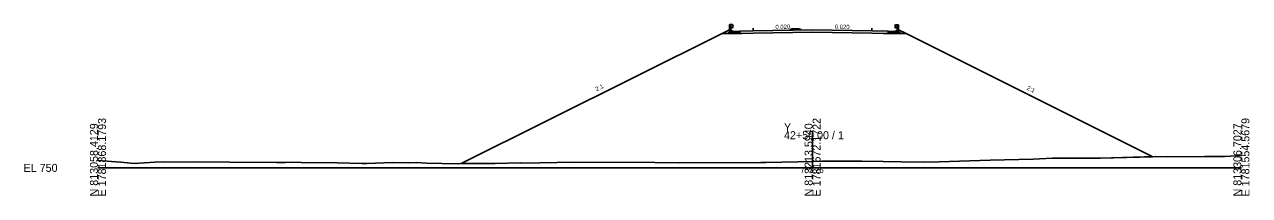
# Model space of a CAD drawing. Extents: x -12583 to 5303, y -44 to 25667.
# Drawn here: x 2874.3 to 3302.8, y 2990.3 to 3050.2 of the extents above; entities that cross this region are included whole.
import ezdxf

# ---------------------------------------------------------------- set-up
doc = ezdxf.new("R2010")
doc.units = 0
for name, color, linetype in [('Exist Cross Section Cell', 7, 'Continuous'), ('Exist XS Center Line Elevation Label', 7, 'Continuous'), ('Exist XS Ground Line', 7, 'Continuous'), ('Prop Conc 5in Monolithic Surface Mount Island', 7, 'Continuous'), ('Prop XS Dump Level', 7, 'Continuous'), ('Prop XS Earthwork Shape', 7, 'Continuous'), ('Prop XS EOT Tick Mark', 7, 'Continuous'), ('Prop XS Finish Grade', 7, 'Continuous'), ('Prop XS Finish Grade CurbGutter', 7, 'Continuous'), ('Prop XS Finish Grade Earthwork', 7, 'Continuous'), ('Prop XS Finish Grade Paved Shoulder', 7, 'Continuous'), ('Prop XS Finish Grade Pavement', 7, 'Continuous'), ('Prop XS Guardrail', 7, 'Continuous'), ('Prop XS Pvmt Edge Slope', 7, 'Continuous'), ('Prop XS SE Text', 7, 'Continuous'), ('Prop XS Side Slope Text', 7, 'Continuous'), ('Prop XS Subgrade CurbGutter', 7, 'Continuous'), ('Prop XS Subgrade Earthwork', 7, 'Continuous')]:
    doc.layers.add(name, color=color, linetype=linetype)

msp = doc.modelspace()

# ---------------------------------------------------------------- linework, layer by layer
at = {"layer": 'Exist Cross Section Cell'}
for p, q in [((3150, 3000), (3150, 3012.85)), ((2900, 3000), (3150, 3000)), ((3150, 3000), (3300, 3000))]:
    msp.add_line(p, q, dxfattribs=at)
at = {"layer": 'Exist XS Ground Line'}
for p, q in [((3294.2, 3004), (3300, 3004.28)), ((2900, 3002.64), (2907.99, 3001.98)), ((2907.99, 3001.98), (2912.67, 3001.49)), ((2912.67, 3001.49), (2919.88, 3001.96)), ((2919.88, 3001.96), (2923.39, 3002.14)), ((2923.39, 3002.14), (2932.14, 3002.04)), ((2932.14, 3002.04), (2934.84, 3002.06)), ((2934.84, 3002.06), (2946.08, 3002)), ((2946.08, 3002), (2962.58, 3001.93)), ((2962.58, 3001.93), (2965.66, 3001.88)), ((2965.66, 3001.88), (2967.65, 3001.95)), ((2967.65, 3001.95), (2971.09, 3001.87)), ((2971.09, 3001.87), (2983.73, 3001.78)), ((2983.73, 3001.78), (2992.42, 3001.51)), ((2992.42, 3001.51), (2993.18, 3001.5)), ((2993.18, 3001.5), (2994.07, 3001.49)), ((2994.07, 3001.49), (3003.1, 3001.84)), ((3003.1, 3001.84), (3008.81, 3001.75)), ((3008.81, 3001.75), (3011.36, 3001.83)), ((3011.36, 3001.83), (3014.98, 3001.68)), ((3014.98, 3001.68), (3025.79, 3001.47)), ((3025.79, 3001.47), (3038.97, 3001.58)), ((3038.97, 3001.58), (3047.75, 3001.78)), ((3047.75, 3001.78), (3048.64, 3001.61)), ((3048.64, 3001.61), (3066.53, 3002.05)), ((3066.53, 3002.05), (3094.86, 3001.86)), ((3094.86, 3001.86), (3103.38, 3001.81)), ((3103.38, 3001.81), (3131.91, 3001.9)), ((3131.91, 3001.9), (3132.7, 3001.9)), ((3132.7, 3001.9), (3133.6, 3001.91)), ((3133.6, 3001.91), (3144.89, 3002.16)), ((3144.89, 3002.16), (3150, 3002.25)), ((3150, 3002.25), (3153.26, 3002.3)), ((3153.26, 3002.3), (3159.58, 3002.33)), ((3159.58, 3002.33), (3167.17, 3002.31)), ((3167.17, 3002.31), (3174.64, 3002.27)), ((3174.64, 3002.27), (3181.1, 3002.16)), ((3181.1, 3002.16), (3188.89, 3001.97)), ((3188.89, 3001.97), (3194.3, 3002.12)), ((3194.3, 3002.12), (3212.11, 3002.67)), ((3212.11, 3002.67), (3227.2, 3003.1)), ((3227.2, 3003.1), (3233.88, 3003.43)), ((3233.88, 3003.43), (3246.46, 3003.35)), ((3246.46, 3003.35), (3250.71, 3003.43)), ((3250.71, 3003.43), (3269.82, 3003.93)), ((3269.82, 3003.93), (3274.03, 3003.9)), ((3274.03, 3003.9), (3287.22, 3003.93)), ((3287.22, 3003.93), (3292.32, 3003.94)), ((3292.32, 3003.94), (3294.2, 3004))]:
    msp.add_line(p, q, dxfattribs=at)
at = {"layer": 'Prop Conc 5in Monolithic Surface Mount Island'}
for p, q in [((3142, 3048.39), (3142.74, 3048.66)), ((3142, 3048.22), (3142, 3048.39)), ((3142.74, 3048.66), (3143.99, 3048.71)), ((3145.24, 3048.71), (3143.99, 3048.71)), ((3146, 3048.47), (3145.24, 3048.71)), ((3146, 3048.3), (3146, 3048.47))]:
    msp.add_line(p, q, dxfattribs=at)
at = {"layer": 'Prop XS Dump Level'}
for p, q in [((3129.25, 3047.97), (3150, 3048.38)), ((3150, 3048.38), (3170.75, 3047.97))]:
    msp.add_line(p, q, dxfattribs=at)
at = {"layer": 'Prop XS Earthwork Shape'}
msp.add_lwpolyline([(3174.64, 3002.27), (3181.1, 3002.16), (3188.89, 3001.97), (3194.3, 3002.12), (3212.11, 3002.67), (3227.2, 3003.1), (3233.88, 3003.43), (3246.46, 3003.35), (3250.71, 3003.43), (3268.99, 3003.91), (3182.68, 3047.06), (3180.81, 3047.06), (3176.42, 3047.06), (3174.75, 3047.1), (3170.75, 3047.18), (3150, 3047.59), (3129.25, 3047.18), (3125.25, 3047.1), (3124.58, 3047.08), (3120.18, 3047.08), (3118.31, 3047.08), (3027.11, 3001.48), (3038.97, 3001.58), (3047.75, 3001.78), (3048.64, 3001.61), (3066.53, 3002.05), (3094.86, 3001.86), (3103.38, 3001.81), (3131.91, 3001.9), (3132.7, 3001.9), (3133.6, 3001.91), (3144.89, 3002.16), (3150, 3002.25), (3153.26, 3002.3), (3159.58, 3002.33), (3167.17, 3002.31)], close=True, dxfattribs=at)
at = {"layer": 'Prop XS EOT Tick Mark'}
for p, q in [((3129.25, 3047.97), (3129.25, 3048.97)), ((3170.75, 3047.97), (3170.75, 3048.97))]:
    msp.add_line(p, q, dxfattribs=at)
at = {"layer": 'Prop XS Finish Grade'}
for p, q in [((3120.97, 3048.41), (3118.31, 3047.08)), ((3121.56, 3048.12), (3120.97, 3048.41)), ((3179.44, 3048.1), (3180.02, 3048.39)), ((3182.68, 3047.06), (3180.02, 3048.39))]:
    msp.add_line(p, q, dxfattribs=at)
at = {"layer": 'Prop XS Finish Grade CurbGutter'}
for p, q in [((3122.25, 3047.78), (3121.56, 3048.12)), ((3124.58, 3047.87), (3122.25, 3047.78)), ((3176.42, 3047.86), (3178.75, 3047.76)), ((3178.75, 3047.76), (3179.44, 3048.1))]:
    msp.add_line(p, q, dxfattribs=at)
at = {"layer": 'Prop XS Finish Grade Earthwork'}
for p, q in [((3118.31, 3047.08), (3027.11, 3001.48)), ((3182.68, 3047.06), (3268.99, 3003.91))]:
    msp.add_line(p, q, dxfattribs=at)
at = {"layer": 'Prop XS Finish Grade Paved Shoulder'}
for p, q in [((3129.25, 3047.97), (3124.58, 3047.87)), ((3170.75, 3047.97), (3176.42, 3047.86))]:
    msp.add_line(p, q, dxfattribs=at)
at = {"layer": 'Prop XS Finish Grade Pavement'}
for p, q in [((3129.25, 3047.97), (3150, 3048.38)), ((3150, 3048.38), (3170.75, 3047.97)), ((3150, 3048.38), (3170.75, 3047.97))]:
    msp.add_line(p, q, dxfattribs=at)
at = {"layer": 'Prop XS Guardrail'}
for p, q in [((3120.93, 3050.18), (3121.43, 3050.18)), ((3120.93, 3047.68), (3120.93, 3050.18)), ((3121.43, 3050.18), (3121.93, 3050.18)), ((3121.43, 3050.18), (3121.43, 3047.68)), ((3121.93, 3049.04), (3121.43, 3049.04)), ((3121.93, 3050.18), (3122.22, 3049.98)), ((3122.22, 3049.86), (3121.93, 3049.66)), ((3121.93, 3049.66), (3121.93, 3049.56)), ((3121.93, 3049.56), (3122.22, 3049.36)), ((3122.22, 3049.24), (3121.93, 3049.04)), ((3122.22, 3049.98), (3122.25, 3049.92)), ((3122.25, 3049.92), (3122.22, 3049.86)), ((3122.22, 3049.36), (3122.25, 3049.3)), ((3122.25, 3049.3), (3122.22, 3049.24)), ((3178.78, 3049.96), (3178.75, 3049.9)), ((3178.75, 3049.9), (3178.78, 3049.84)), ((3178.78, 3049.34), (3178.75, 3049.28)), ((3178.75, 3049.28), (3178.78, 3049.22)), ((3179.07, 3050.16), (3178.78, 3049.96)), ((3178.78, 3049.84), (3179.07, 3049.64)), ((3179.07, 3049.54), (3178.78, 3049.34)), ((3178.78, 3049.22), (3179.07, 3049.02)), ((3179.57, 3050.16), (3179.07, 3050.16)), ((3179.07, 3049.64), (3179.07, 3049.54)), ((3179.07, 3049.02), (3179.57, 3049.02)), ((3180.07, 3050.16), (3179.57, 3050.16)), ((3179.57, 3050.16), (3179.57, 3047.66)), ((3180.07, 3047.66), (3180.07, 3050.16))]:
    msp.add_line(p, q, dxfattribs=at)
at = {"layer": 'Prop XS Pvmt Edge Slope'}
for p, q in [((3120.56, 3047.45), (3120.18, 3047.08)), ((3121.56, 3047.45), (3120.56, 3047.45)), ((3179.44, 3047.44), (3180.44, 3047.44)), ((3180.44, 3047.44), (3180.81, 3047.06))]:
    msp.add_line(p, q, dxfattribs=at)
at = {"layer": 'Prop XS Subgrade CurbGutter'}
for p, q in [((3121.56, 3047.45), (3121.56, 3048.12)), ((3124.58, 3047.45), (3121.56, 3047.45)), ((3124.58, 3047.87), (3124.58, 3047.45)), ((3176.42, 3047.86), (3176.42, 3047.44)), ((3176.42, 3047.44), (3179.44, 3047.44)), ((3179.44, 3047.44), (3179.44, 3048.1))]:
    msp.add_line(p, q, dxfattribs=at)
at = {"layer": 'Prop XS Subgrade Earthwork'}
for p, q in [((3120.18, 3047.08), (3118.31, 3047.08)), ((3124.58, 3047.08), (3120.18, 3047.08)), ((3125.25, 3047.1), (3124.58, 3047.08)), ((3129.25, 3047.18), (3125.25, 3047.1)), ((3150, 3047.59), (3129.25, 3047.18)), ((3170.75, 3047.18), (3150, 3047.59)), ((3170.75, 3047.18), (3174.75, 3047.1)), ((3174.75, 3047.1), (3176.42, 3047.06)), ((3176.42, 3047.06), (3180.81, 3047.06)), ((3180.81, 3047.06), (3182.68, 3047.06))]:
    msp.add_line(p, q, dxfattribs=at)

# ---------------------------------------------------------------- texts
at = {"layer": 'Exist Cross Section Cell'}
for s, p in [('E 1781868.1793', (2902.8, 2990)), ('E 1781672.1722', (3152.8, 2990)), ('E 1781554.5679', (3302.8, 2990)), ('N 813058.4129', (2900, 2990)), ('N 813213.5940', (3150, 2990)), ('N 813306.7027', (3300, 2990))]:
    msp.add_text(s, height=2.8, rotation=90, dxfattribs=at).set_placement(p)
for s, p in [('Y', (3140, 3012.85)), ('42+50.00 / 1', (3140, 3010.05)), ('EL 750', (2874, 2998.6))]:
    msp.add_text(s, height=2.8, dxfattribs=at).set_placement(p)
at = {"layer": 'Exist XS Center Line Elevation Label'}
msp.add_text('752.25', height=2, dxfattribs=at).set_placement((3145.74, 2998.25))
at = {"layer": 'Prop XS SE Text'}
for rotation, p in [(1.1458, (3137, 3048.62)), (358.8542, (3157.75, 3048.73)), (358.8542, (3157.75, 3048.73))]:
    msp.add_text('0.020', height=1.5, rotation=rotation, dxfattribs=at).set_placement(p)
at = {"layer": 'Prop XS Side Slope Text'}
for rotation, p in [(26.5651, (3074.45, 3026.83)), (333.4349, (3224.77, 3027.5))]:
    msp.add_text('2:1', height=1.5, rotation=rotation, dxfattribs=at).set_placement(p)

doc.saveas('drawing.dxf')
